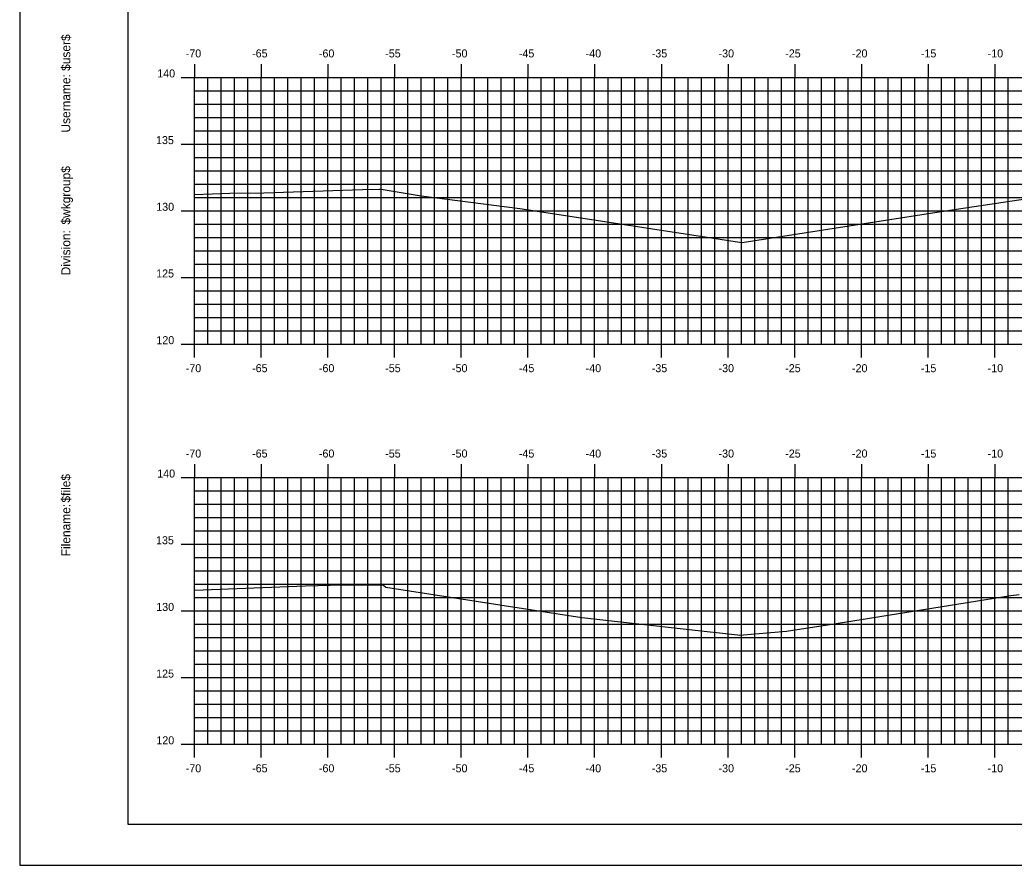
# Model space of a CAD drawing. Extents: x 850630 to 850801, y 365624 to 365734.
# Drawn here: x 850629.6 to 850704.2, y 365624 to 365687.3 of the extents above; entities that cross this region are included whole.
import ezdxf

# ---------------------------------------------------------------- set-up
doc = ezdxf.new("R2010")
doc.units = 0
for name, color, linetype in [('BORDER', 7, 'Continuous'), ('H_V ANNOTATION', 7, 'Continuous'), ('MAJOR', 7, 'Continuous'), ('MINOR', 7, 'Continuous'), ('PLOT BOUNDARY', 7, 'Continuous'), ('S_Roadway_Centerline', 7, 'Continuous')]:
    doc.layers.add(name, color=color, linetype=linetype)

msp = doc.modelspace()

# ---------------------------------------------------------------- linework, layer by layer
at = {"layer": 'BORDER'}
msp.add_lwpolyline([(850637.74, 365627.027), (850797.74, 365627.027), (850797.74, 365732.027), (850637.74, 365732.027)], close=True, dxfattribs=at)
at = {"layer": 'MAJOR'}
for p, q in [((850642.739, 365684.029), (850642.739, 365683.027)), ((850647.739, 365684.029), (850647.739, 365683.027)), ((850652.739, 365684.029), (850652.739, 365683.027)), ((850657.739, 365684.029), (850657.739, 365683.027)), ((850662.739, 365684.029), (850662.739, 365683.027)), ((850667.739, 365684.029), (850667.739, 365683.027)), ((850672.739, 365684.029), (850672.739, 365683.027)), ((850677.739, 365684.029), (850677.739, 365683.027)), ((850682.739, 365684.029), (850682.739, 365683.027)), ((850687.739, 365684.029), (850687.739, 365683.027)), ((850692.739, 365684.029), (850692.739, 365683.027)), ((850697.739, 365684.029), (850697.739, 365683.027)), ((850702.739, 365684.029), (850702.739, 365683.027)), ((850641.737, 365683.027), (850642.739, 365683.027)), ((850642.739, 365683.027), (850782.739, 365683.027)), ((850642.739, 365663.027), (850642.739, 365683.027)), ((850642.739, 365663.027), (850642.739, 365683.027)), ((850642.739, 365683.027), (850782.739, 365683.027)), ((850647.739, 365663.027), (850647.739, 365683.027)), ((850652.739, 365663.027), (850652.739, 365683.027)), ((850657.739, 365663.027), (850657.739, 365683.027)), ((850662.739, 365663.027), (850662.739, 365683.027)), ((850667.739, 365663.027), (850667.739, 365683.027)), ((850672.739, 365663.027), (850672.739, 365683.027)), ((850677.739, 365663.027), (850677.739, 365683.027)), ((850682.739, 365663.027), (850682.739, 365683.027)), ((850687.739, 365663.027), (850687.739, 365683.027)), ((850692.739, 365663.027), (850692.739, 365683.027)), ((850697.739, 365663.027), (850697.739, 365683.027)), ((850702.739, 365663.027), (850702.739, 365683.027)), ((850641.737, 365678.027), (850642.739, 365678.027)), ((850642.739, 365678.027), (850782.739, 365678.027)), ((850641.737, 365673.027), (850642.739, 365673.027)), ((850642.739, 365673.027), (850782.739, 365673.027)), ((850641.737, 365668.027), (850642.739, 365668.027)), ((850642.739, 365668.027), (850782.739, 365668.027)), ((850641.737, 365663.027), (850642.739, 365663.027)), ((850642.739, 365663.027), (850782.739, 365663.027)), ((850642.739, 365663.027), (850782.739, 365663.027)), ((850642.739, 365662.025), (850642.739, 365663.027)), ((850647.739, 365662.025), (850647.739, 365663.027)), ((850652.739, 365662.025), (850652.739, 365663.027)), ((850657.739, 365662.025), (850657.739, 365663.027)), ((850662.739, 365662.025), (850662.739, 365663.027)), ((850667.739, 365662.025), (850667.739, 365663.027)), ((850672.739, 365662.025), (850672.739, 365663.027)), ((850677.739, 365662.025), (850677.739, 365663.027)), ((850682.739, 365662.025), (850682.739, 365663.027)), ((850687.739, 365662.025), (850687.739, 365663.027)), ((850692.739, 365662.025), (850692.739, 365663.027)), ((850697.739, 365662.025), (850697.739, 365663.027)), ((850702.739, 365662.025), (850702.739, 365663.027)), ((850642.739, 365654.029), (850642.739, 365653.027)), ((850647.739, 365654.029), (850647.739, 365653.027)), ((850652.739, 365654.029), (850652.739, 365653.027)), ((850657.739, 365654.029), (850657.739, 365653.027)), ((850662.739, 365654.029), (850662.739, 365653.027)), ((850667.739, 365654.029), (850667.739, 365653.027)), ((850672.739, 365654.029), (850672.739, 365653.027)), ((850677.739, 365654.029), (850677.739, 365653.027)), ((850682.739, 365654.029), (850682.739, 365653.027)), ((850687.739, 365654.029), (850687.739, 365653.027)), ((850692.739, 365654.029), (850692.739, 365653.027)), ((850697.739, 365654.029), (850697.739, 365653.027)), ((850702.739, 365654.029), (850702.739, 365653.027)), ((850641.737, 365653.027), (850642.739, 365653.027)), ((850642.739, 365653.027), (850782.739, 365653.027)), ((850642.739, 365633.027), (850642.739, 365653.027)), ((850642.739, 365633.027), (850642.739, 365653.027)), ((850642.739, 365653.027), (850782.739, 365653.027)), ((850647.739, 365633.027), (850647.739, 365653.027)), ((850652.739, 365633.027), (850652.739, 365653.027)), ((850657.739, 365633.027), (850657.739, 365653.027)), ((850662.739, 365633.027), (850662.739, 365653.027)), ((850667.739, 365633.027), (850667.739, 365653.027)), ((850672.739, 365633.027), (850672.739, 365653.027)), ((850677.739, 365633.027), (850677.739, 365653.027)), ((850682.739, 365633.027), (850682.739, 365653.027)), ((850687.739, 365633.027), (850687.739, 365653.027)), ((850692.739, 365633.027), (850692.739, 365653.027)), ((850697.739, 365633.027), (850697.739, 365653.027)), ((850702.739, 365633.027), (850702.739, 365653.027)), ((850641.737, 365648.027), (850642.739, 365648.027)), ((850642.739, 365648.027), (850782.739, 365648.027)), ((850641.737, 365643.027), (850642.739, 365643.027)), ((850642.739, 365643.027), (850782.739, 365643.027)), ((850641.737, 365638.027), (850642.739, 365638.027)), ((850642.739, 365638.027), (850782.739, 365638.027)), ((850641.737, 365633.027), (850642.739, 365633.027)), ((850642.739, 365633.027), (850782.739, 365633.027)), ((850642.739, 365633.027), (850782.739, 365633.027)), ((850642.739, 365632.025), (850642.739, 365633.027)), ((850647.739, 365632.025), (850647.739, 365633.027)), ((850652.739, 365632.025), (850652.739, 365633.027)), ((850657.739, 365632.025), (850657.739, 365633.027)), ((850662.739, 365632.025), (850662.739, 365633.027)), ((850667.739, 365632.025), (850667.739, 365633.027)), ((850672.739, 365632.025), (850672.739, 365633.027)), ((850677.739, 365632.025), (850677.739, 365633.027)), ((850682.739, 365632.025), (850682.739, 365633.027)), ((850687.739, 365632.025), (850687.739, 365633.027)), ((850692.739, 365632.025), (850692.739, 365633.027)), ((850697.739, 365632.025), (850697.739, 365633.027)), ((850702.739, 365632.025), (850702.739, 365633.027))]:
    msp.add_line(p, q, dxfattribs=at)
at = {"layer": 'MINOR'}
for p, q in [((850643.739, 365663.027), (850643.739, 365683.027)), ((850644.739, 365663.027), (850644.739, 365683.027)), ((850645.739, 365663.027), (850645.739, 365683.027)), ((850646.739, 365663.027), (850646.739, 365683.027)), ((850648.739, 365663.027), (850648.739, 365683.027)), ((850649.739, 365663.027), (850649.739, 365683.027)), ((850650.739, 365663.027), (850650.739, 365683.027)), ((850651.739, 365663.027), (850651.739, 365683.027)), ((850653.739, 365663.027), (850653.739, 365683.027)), ((850654.739, 365663.027), (850654.739, 365683.027)), ((850655.739, 365663.027), (850655.739, 365683.027)), ((850656.739, 365663.027), (850656.739, 365683.027)), ((850658.739, 365663.027), (850658.739, 365683.027)), ((850659.739, 365663.027), (850659.739, 365683.027)), ((850660.739, 365663.027), (850660.739, 365683.027)), ((850661.739, 365663.027), (850661.739, 365683.027)), ((850663.739, 365663.027), (850663.739, 365683.027)), ((850664.739, 365663.027), (850664.739, 365683.027)), ((850665.739, 365663.027), (850665.739, 365683.027)), ((850666.739, 365663.027), (850666.739, 365683.027)), ((850668.739, 365663.027), (850668.739, 365683.027)), ((850669.739, 365663.027), (850669.739, 365683.027)), ((850670.739, 365663.027), (850670.739, 365683.027)), ((850671.739, 365663.027), (850671.739, 365683.027)), ((850673.739, 365663.027), (850673.739, 365683.027)), ((850674.739, 365663.027), (850674.739, 365683.027)), ((850675.739, 365663.027), (850675.739, 365683.027)), ((850676.739, 365663.027), (850676.739, 365683.027)), ((850678.739, 365663.027), (850678.739, 365683.027)), ((850679.739, 365663.027), (850679.739, 365683.027)), ((850680.739, 365663.027), (850680.739, 365683.027)), ((850681.739, 365663.027), (850681.739, 365683.027)), ((850683.739, 365663.027), (850683.739, 365683.027)), ((850684.739, 365663.027), (850684.739, 365683.027)), ((850685.739, 365663.027), (850685.739, 365683.027)), ((850686.739, 365663.027), (850686.739, 365683.027)), ((850688.739, 365663.027), (850688.739, 365683.027)), ((850689.739, 365663.027), (850689.739, 365683.027)), ((850690.739, 365663.027), (850690.739, 365683.027)), ((850691.739, 365663.027), (850691.739, 365683.027)), ((850693.739, 365663.027), (850693.739, 365683.027)), ((850694.739, 365663.027), (850694.739, 365683.027)), ((850695.739, 365663.027), (850695.739, 365683.027)), ((850696.739, 365663.027), (850696.739, 365683.027)), ((850698.739, 365663.027), (850698.739, 365683.027)), ((850699.739, 365663.027), (850699.739, 365683.027)), ((850700.739, 365663.027), (850700.739, 365683.027)), ((850701.739, 365663.027), (850701.739, 365683.027)), ((850703.739, 365663.027), (850703.739, 365683.027)), ((850642.739, 365682.027), (850782.739, 365682.027)), ((850642.739, 365682.027), (850643.741, 365682.027)), ((850642.739, 365681.027), (850782.739, 365681.027)), ((850642.739, 365681.027), (850643.741, 365681.027)), ((850642.739, 365680.027), (850782.739, 365680.027)), ((850642.739, 365680.027), (850643.741, 365680.027)), ((850642.739, 365679.027), (850782.739, 365679.027)), ((850642.739, 365679.027), (850643.741, 365679.027)), ((850642.739, 365677.027), (850782.739, 365677.027)), ((850642.739, 365677.027), (850643.741, 365677.027)), ((850642.739, 365676.027), (850782.739, 365676.027)), ((850642.739, 365676.027), (850643.741, 365676.027)), ((850642.739, 365675.027), (850782.739, 365675.027)), ((850642.739, 365675.027), (850643.741, 365675.027)), ((850642.739, 365674.027), (850782.739, 365674.027)), ((850642.739, 365674.027), (850643.741, 365674.027)), ((850642.739, 365672.027), (850782.739, 365672.027)), ((850642.739, 365672.027), (850643.741, 365672.027)), ((850642.739, 365671.027), (850782.739, 365671.027)), ((850642.739, 365671.027), (850643.741, 365671.027)), ((850642.739, 365670.027), (850782.739, 365670.027)), ((850642.739, 365670.027), (850643.741, 365670.027)), ((850642.739, 365669.027), (850782.739, 365669.027)), ((850642.739, 365669.027), (850643.741, 365669.027)), ((850642.739, 365667.027), (850782.739, 365667.027)), ((850642.739, 365667.027), (850643.741, 365667.027)), ((850642.739, 365666.027), (850782.739, 365666.027)), ((850642.739, 365666.027), (850643.741, 365666.027)), ((850642.739, 365665.027), (850782.739, 365665.027)), ((850642.739, 365665.027), (850643.741, 365665.027)), ((850642.739, 365664.027), (850782.739, 365664.027)), ((850642.739, 365664.027), (850643.741, 365664.027)), ((850643.739, 365633.027), (850643.739, 365653.027)), ((850644.739, 365633.027), (850644.739, 365653.027)), ((850645.739, 365633.027), (850645.739, 365653.027)), ((850646.739, 365633.027), (850646.739, 365653.027)), ((850648.739, 365633.027), (850648.739, 365653.027)), ((850649.739, 365633.027), (850649.739, 365653.027)), ((850650.739, 365633.027), (850650.739, 365653.027)), ((850651.739, 365633.027), (850651.739, 365653.027)), ((850653.739, 365633.027), (850653.739, 365653.027)), ((850654.739, 365633.027), (850654.739, 365653.027)), ((850655.739, 365633.027), (850655.739, 365653.027)), ((850656.739, 365633.027), (850656.739, 365653.027)), ((850658.739, 365633.027), (850658.739, 365653.027)), ((850659.739, 365633.027), (850659.739, 365653.027)), ((850660.739, 365633.027), (850660.739, 365653.027)), ((850661.739, 365633.027), (850661.739, 365653.027)), ((850663.739, 365633.027), (850663.739, 365653.027)), ((850664.739, 365633.027), (850664.739, 365653.027)), ((850665.739, 365633.027), (850665.739, 365653.027)), ((850666.739, 365633.027), (850666.739, 365653.027)), ((850668.739, 365633.027), (850668.739, 365653.027)), ((850669.739, 365633.027), (850669.739, 365653.027)), ((850670.739, 365633.027), (850670.739, 365653.027)), ((850671.739, 365633.027), (850671.739, 365653.027)), ((850673.739, 365633.027), (850673.739, 365653.027)), ((850674.739, 365633.027), (850674.739, 365653.027)), ((850675.739, 365633.027), (850675.739, 365653.027)), ((850676.739, 365633.027), (850676.739, 365653.027)), ((850678.739, 365633.027), (850678.739, 365653.027)), ((850679.739, 365633.027), (850679.739, 365653.027)), ((850680.739, 365633.027), (850680.739, 365653.027)), ((850681.739, 365633.027), (850681.739, 365653.027)), ((850683.739, 365633.027), (850683.739, 365653.027)), ((850684.739, 365633.027), (850684.739, 365653.027)), ((850685.739, 365633.027), (850685.739, 365653.027)), ((850686.739, 365633.027), (850686.739, 365653.027)), ((850688.739, 365633.027), (850688.739, 365653.027)), ((850689.739, 365633.027), (850689.739, 365653.027)), ((850690.739, 365633.027), (850690.739, 365653.027)), ((850691.739, 365633.027), (850691.739, 365653.027)), ((850693.739, 365633.027), (850693.739, 365653.027)), ((850694.739, 365633.027), (850694.739, 365653.027)), ((850695.739, 365633.027), (850695.739, 365653.027)), ((850696.739, 365633.027), (850696.739, 365653.027)), ((850698.739, 365633.027), (850698.739, 365653.027)), ((850699.739, 365633.027), (850699.739, 365653.027)), ((850700.739, 365633.027), (850700.739, 365653.027)), ((850701.739, 365633.027), (850701.739, 365653.027)), ((850703.739, 365633.027), (850703.739, 365653.027)), ((850642.739, 365652.027), (850782.739, 365652.027)), ((850642.739, 365652.027), (850643.741, 365652.027)), ((850642.739, 365651.027), (850782.739, 365651.027)), ((850642.739, 365651.027), (850643.741, 365651.027)), ((850642.739, 365650.027), (850782.739, 365650.027)), ((850642.739, 365650.027), (850643.741, 365650.027)), ((850642.739, 365649.027), (850782.739, 365649.027)), ((850642.739, 365649.027), (850643.741, 365649.027)), ((850642.739, 365647.027), (850782.739, 365647.027)), ((850642.739, 365647.027), (850643.741, 365647.027)), ((850642.739, 365646.027), (850782.739, 365646.027)), ((850642.739, 365646.027), (850643.741, 365646.027)), ((850642.739, 365645.027), (850782.739, 365645.027)), ((850642.739, 365645.027), (850643.741, 365645.027)), ((850642.739, 365644.027), (850782.739, 365644.027)), ((850642.739, 365644.027), (850643.741, 365644.027)), ((850642.739, 365642.027), (850782.739, 365642.027)), ((850642.739, 365642.027), (850643.741, 365642.027)), ((850642.739, 365641.027), (850782.739, 365641.027)), ((850642.739, 365641.027), (850643.741, 365641.027)), ((850642.739, 365640.027), (850782.739, 365640.027)), ((850642.739, 365640.027), (850643.741, 365640.027)), ((850642.739, 365639.027), (850782.739, 365639.027)), ((850642.739, 365639.027), (850643.741, 365639.027)), ((850642.739, 365637.027), (850782.739, 365637.027)), ((850642.739, 365637.027), (850643.741, 365637.027)), ((850642.739, 365636.027), (850782.739, 365636.027)), ((850642.739, 365636.027), (850643.741, 365636.027)), ((850642.739, 365635.027), (850782.739, 365635.027)), ((850642.739, 365635.027), (850643.741, 365635.027)), ((850642.739, 365634.027), (850782.739, 365634.027)), ((850642.739, 365634.027), (850643.741, 365634.027))]:
    msp.add_line(p, q, dxfattribs=at)
at = {"layer": 'PLOT BOUNDARY'}
msp.add_lwpolyline([(850629.646, 365623.968), (850799.646, 365623.968), (850799.646, 365733.968), (850629.646, 365733.968)], close=True, dxfattribs=at)
at = {"layer": 'S_Roadway_Centerline'}
for points in [[(850642.739, 365674.238), (850645.391, 365674.341), (850647.935, 365674.377), (850655.338, 365674.632), (850656.596, 365674.643), (850656.732, 365674.656), (850659.724, 365674.153), (850667.14, 365673.204), (850683.764, 365670.662), (850683.791, 365670.658), (850683.793, 365670.657), (850683.8, 365670.658), (850698.72, 365672.967), (850701.203, 365673.361), (850709.069, 365674.533)], [(850642.739, 365644.571), (850651.048, 365644.909), (850653.834, 365644.983), (850656.916, 365644.969), (850657.076, 365644.82), (850665.317, 365643.539), (850671.78, 365642.526), (850679.817, 365641.637), (850683.46, 365641.233), (850683.6, 365641.219), (850687.134, 365641.502), (850690.833, 365642.074), (850703.949, 365644.184), (850704.554, 365644.269)]]:
    msp.add_lwpolyline(points, dxfattribs=at)

# ---------------------------------------------------------------- texts
at = {"layer": 'BORDER'}
for s, p in [('$user$', (850633.425, 365683.518)), ('Username:', (850633.425, 365678.895)), ('$wkgroup$', (850633.425, 365671.996)), ('Division:', (850633.425, 365668.193)), ('$file$', (850633.425, 365651.152)), ('Filename:', (850633.425, 365647.125))]:
    msp.add_text(s, height=0.6696, rotation=90, dxfattribs=at).set_placement(p)
at = {"layer": 'H_V ANNOTATION'}
for s, p in [('-70', (850642.081, 365684.527)), ('-65', (850647.057, 365684.527)), ('-60', (850652.065, 365684.527)), ('-55', (850657.036, 365684.527)), ('-50', (850662.044, 365684.527)), ('-45', (850667.057, 365684.527)), ('-40', (850672.065, 365684.527)), ('-35', (850677.02, 365684.527)), ('-30', (850682.028, 365684.527)), ('-25', (850687.025, 365684.527)), ('-20', (850692.033, 365684.527)), ('-15', (850697.196, 365684.527)), ('-10', (850702.204, 365684.527)), ('140', (850639.944, 365683.027)), ('135', (850639.853, 365678.027)), ('130', (850639.869, 365673.027)), ('125', (850639.864, 365668.027)), ('120', (850639.88, 365663.027)), ('-70', (850642.081, 365660.927)), ('-65', (850647.057, 365660.927)), ('-60', (850652.065, 365660.927)), ('-55', (850657.036, 365660.927)), ('-50', (850662.044, 365660.927)), ('-45', (850667.057, 365660.927)), ('-40', (850672.065, 365660.927)), ('-35', (850677.02, 365660.927)), ('-30', (850682.028, 365660.927)), ('-25', (850687.025, 365660.927)), ('-20', (850692.033, 365660.927)), ('-15', (850697.196, 365660.927)), ('-10', (850702.204, 365660.927)), ('-70', (850642.081, 365654.527)), ('-65', (850647.057, 365654.527)), ('-60', (850652.065, 365654.527)), ('-55', (850657.036, 365654.527)), ('-50', (850662.044, 365654.527)), ('-45', (850667.057, 365654.527)), ('-40', (850672.065, 365654.527)), ('-35', (850677.02, 365654.527)), ('-30', (850682.028, 365654.527)), ('-25', (850687.025, 365654.527)), ('-20', (850692.033, 365654.527)), ('-15', (850697.196, 365654.527)), ('-10', (850702.204, 365654.527)), ('140', (850639.944, 365653.027)), ('135', (850639.853, 365648.027)), ('130', (850639.869, 365643.027)), ('125', (850639.864, 365638.027)), ('120', (850639.88, 365633.027)), ('-70', (850642.081, 365630.927)), ('-65', (850647.057, 365630.927)), ('-60', (850652.065, 365630.927)), ('-55', (850657.036, 365630.927)), ('-50', (850662.044, 365630.927)), ('-45', (850667.057, 365630.927)), ('-40', (850672.065, 365630.927)), ('-35', (850677.02, 365630.927)), ('-30', (850682.028, 365630.927)), ('-25', (850687.025, 365630.927)), ('-20', (850692.033, 365630.927)), ('-15', (850697.196, 365630.927)), ('-10', (850702.204, 365630.927))]:
    msp.add_text(s, height=0.6, dxfattribs=at).set_placement(p)
at = {"layer": 'MAJOR'}
for p in [(850642.735, 365663.027), (850642.735, 365633.027)]:
    msp.add_text('-', height=0.006, dxfattribs=at).set_placement(p)

doc.saveas('drawing.dxf')
